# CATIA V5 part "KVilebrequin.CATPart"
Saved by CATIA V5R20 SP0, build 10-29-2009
Part number: K_Vilebrequin
Bounding box of the stored display mesh (mm): x 0 to 24, y 68.993 to 173.9, z 124.874 to 259.015
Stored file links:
  C:\Users\thinkmotion1\Desktop\Khaled_IAO_Pack2\IAO_2010_1392_rragonneau\CATIA_1392_rragonneau\KVilebrequin.CATPart
  D:\Documents\Scolaire\MM2\IAO\Squelette\Product1.CATProduct
  C:\Users\thinkmotion1\Desktop\Khaled_IAO_Pack2\IAO_2010_1392_rragonneau\CATIA_1392_rragonneau\KSquelette de base.CATPart
  C:\Users\thinkmotion1\Desktop\Khaled_IAO_Pack2\IAO_2010_1392_rragonneau\CATIA_1392_rragonneau\KSquelette vilebrequin.CATPart
  C:\Users\ThinkMotion\Desktop\EU_thinkMotion\iao\IAO_MMS_Groupe1\Problemes\rragonneau\rragonneau\Squelette bati.CATPart
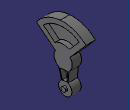
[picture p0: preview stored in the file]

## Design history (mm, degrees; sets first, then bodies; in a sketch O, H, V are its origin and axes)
External parameters (linked from other documents)
  External.diam_axe_bielle = 20 mm
Set1
  Sketch1 on Plane1, origin (0, 0, 0), H (0, 1, 0), V (0, 0, 1)
    axis line L1 (132.2538, 111.9593) -> (118.7784, 265.5117)
    reference projected line E1 (125.5136, 188.765) -> (129.8267, 139.6164) from Line1
    arc A1 centre (125.5161, 188.7355) radius 70.2829 from (173.9003, 239.7126) to (119.3719, 258.7493) ccw
    point P3 (125.5161, 188.7355)
    point P4 (173.9003, 239.7126)
    point P5 (119.3719, 258.7493)
    line L2 (173.9003, 239.7126) -> (139.9837, 201.111)
    point P6 (173.9003, 239.7126)
    point P7 (139.9837, 201.111)
    arc A2 centre (125.5161, 188.7355) radius 19.0385 from (137.7676, 174.1627) to (139.9837, 201.111) ccw
    point P8 (139.9837, 201.111)
    point P9 (137.7676, 174.1627)
    arc A3 centre (129.8872, 138.9269) radius 14.054 from (131.1159, 124.9267) to (135.7186, 151.714) ccw
    point P10 (129.8872, 138.9269)
    point P11 (131.1159, 124.9267)
    point P12 (135.7186, 151.714)
    line L3 (135.7186, 151.714) -> (137.7676, 174.1627)
    point P13 (119.3719, 258.7493)
    point P14 (68.9927, 230.5062)
    arc A4 centre (125.5161, 188.7355) radius 70.2829 from (68.9927, 230.5062) to (119.3719, 258.7493) cw
    point P16 (109.1142, 198.402)
    point P17 (68.9927, 230.5062)
    line L4 (68.9927, 230.5062) -> (109.1142, 198.402)
    point P18 (109.1142, 198.402)
    point P19 (115.9902, 172.2515)
    point P20 (125.5161, 188.7355)
    arc A5 centre (125.5161, 188.7355) radius 19.0385 from (115.9902, 172.2515) to (109.1142, 198.402) cw
    point P21 (115.9902, 172.2515)
    point P22 (121.9178, 150.5029)
    line L5 (121.9178, 150.5029) -> (115.9902, 172.2515)
    point P23 (121.9178, 150.5029)
    point P24 (131.1159, 124.9267)
    point P25 (129.8872, 138.9269)
    arc A6 centre (129.8872, 138.9269) radius 14.054 from (131.1159, 124.9267) to (121.9178, 150.5029) cw
    reference projected point E2 (125.5161, 188.7355) from Point2
    reference projected point E3 (129.8872, 138.9269) from vertex of DatumPoint1
    radius A2 = 19.0385
    radius A3 = 14.054
    radius A1 = 70.2829
    angle L2 L1 = 46.3188
    distance P9 L1 = 10.9306
    distance P7 L1 = 15.4941
    coincidence: L1 E1, L1 P5, P6 A1, P8 L2, A2 P7, P10 L1, P11 L1, P4 P6, P5 P13, P7 P8, P11 P24, P14 P17, P16 P18, P19 P21, P22 P23, P20 E2, P25 E3
    midpoint: P3 L1
    symmetry: P5 P13 L1, P4 P14 L1, A1 A4 L1, P7 P16 L1, P6 P17 L1, L2 L4 L1, P8 P18 L1, P9 P19 L1, A2 A5 L1, P9 P21 L1, P12 P22 L1, L3 L5 L1, P12 P23 L1, P11 P24 L1, A3 A6 L1
Set2
  Plane1: linked copy from another document
  Line1: linked copy from another document
  Point1: linked copy from another document
  Point2: linked copy from another document
  DatumPoint1: linked copy from another document
Body1 (main body)
  Pad1: profile Sketch1, direction (1, 0, 0), length 20
  Sketch2 on end face of Pad1, origin (20, 0, 0), H (0, 1, 0), V (0, 0, 1)
    circle A1 centre (129.8872, 138.9269) radius 5
    reference projected arc E1 centre (129.8872, 138.9269) radius 14.054 from (131.1159, 124.9267) to (135.7186, 151.714) ccw from edge [face of Pad1 from Sketch1.A3 | end face of Pad1]
    radius A1 = 5 {= External.diam_axe_bielle /4}
    concentricity: A1 E1
  Pad2: profile Sketch2, direction (1, 0, 0), length 4
  Sketch3 on end face of Pad1, origin (20, 0, 0), H (0, 1, 0), V (0, 0, 1)
    arc A1 centre (125.5158, 188.7351) radius 60.2834 from (159.529, 238.5066) to (83.354, 231.8219) ccw
    point P1 (125.5158, 188.7351)
    reference projected arc E1 centre (125.5161, 188.7355) radius 19.0385 from (137.7676, 174.1627) to (139.9837, 201.111) ccw from edge [face of Pad1 from Sketch1.A2 | end face of Pad1]
    reference projected arc E2 centre (125.5161, 188.7355) radius 70.2829 from (173.9003, 239.7126) to (119.3719, 258.7493) ccw from edge [face of Pad1 from Sketch1.A1 | end face of Pad1]
    arc A2 centre (125.5158, 188.7351) radius 29.039 from (138.5835, 214.6677) to (108.1315, 211.9956) ccw
    reference projected arc E3 centre (125.5161, 188.7355) radius 19.0385 from (137.7676, 174.1627) to (139.9837, 201.111) ccw from edge [face of Pad1 from Sketch1.A2 | end face of Pad1]
    line L1 (138.5835, 214.6677) -> (159.529, 238.5066)
    reference projected line E4 (139.9837, 201.111) -> (173.9003, 239.7126) from edge [face of Pad1 from Sketch1.L2 | end face of Pad1]
    line L2 (83.354, 231.8219) -> (108.1315, 211.9956)
    reference projected line E5 (68.9927, 230.5062) -> (109.1142, 198.402) from edge [face of Pad1 from Sketch1.L4 | end face of Pad1]
    line L3 (118.3812, 171.0845) -> (123.7058, 151.5485)
    point P6 (118.3812, 171.0845)
    point P7 (123.7058, 151.5485)
    line L4 (123.7058, 151.5485) -> (133.7758, 152.4323)
    point P8 (133.7758, 152.4323)
    line L5 (133.7758, 152.4323) -> (135.6164, 172.597)
    point P9 (135.6164, 172.597)
    line L6 (135.6164, 172.597) -> (118.3812, 171.0845)
    reference projected line E6 (115.9902, 172.2515) -> (121.9178, 150.5029) from edge [face of Pad1 from Sketch1.L5 | end face of Pad1]
    reference projected line E7 (135.7186, 151.714) -> (137.7676, 174.1627) from edge [face of Pad1 from Sketch1.L3 | end face of Pad1]
    reference projected arc E8 centre (129.8872, 138.9269) radius 14.054 from (121.9178, 150.5029) to (131.1159, 124.9267) ccw from edge [face of Pad1 from Sketch1.A6 | end face of Pad1]
    reference projected arc E9 centre (129.8872, 138.9269) radius 14.054 from (131.1159, 124.9267) to (135.7186, 151.714) ccw from edge [face of Pad1 from Sketch1.A3 | end face of Pad1]
    reference projected arc E10 centre (125.5161, 188.7355) radius 19.0385 from (137.7676, 174.1627) to (139.9837, 201.111) ccw from edge [face of Pad1 from Sketch1.A2 | end face of Pad1]
    reference projected arc E11 centre (125.5161, 188.7355) radius 19.0385 from (109.1142, 198.402) to (115.9902, 172.2515) ccw from edge [face of Pad1 from Sketch1.A5 | end face of Pad1]
    distance P1 E1 = 19.039
    distance A1 E2 = 10
    distance A2 E3 = 10
    distance L1 E4 = 10
    distance L2 E5 = 10
    distance L3 E6 = 2
    distance L5 E7 = 2
    distance P7 E8 = 0
    distance P8 E9 = 0
    distance P9 E10 = 0
    distance P6 E11 = 0
  Pocket1: profile Sketch3, direction (-1, 0, 0), length 10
